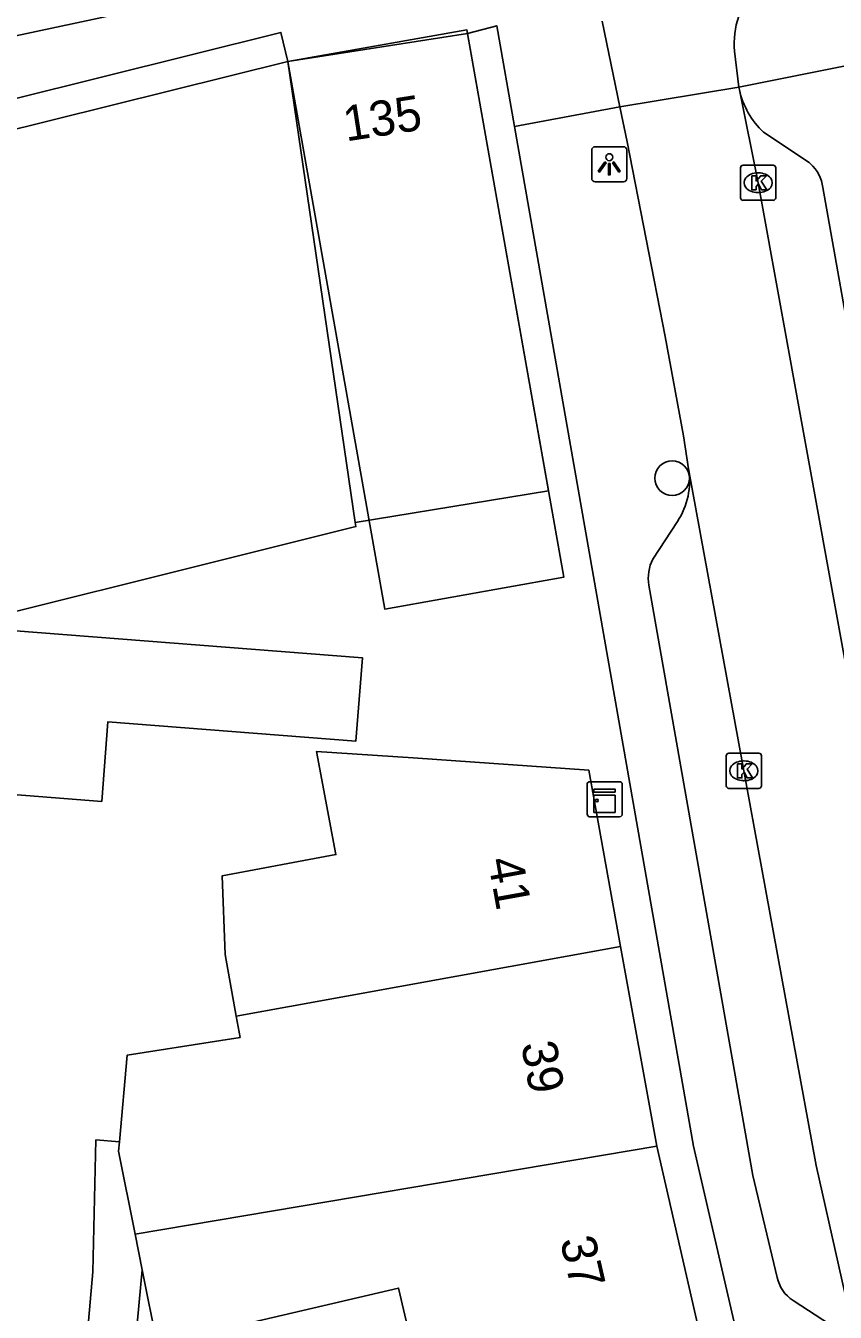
# Model space of a CAD drawing. Extents: x 160861 to 161308, y 384024 to 384878.
# Drawn here: x 160956.66 to 160979.67, y 384818.67 to 384855.22 of the extents above; entities that cross this region are included whole.
import ezdxf

# ---------------------------------------------------------------- set-up
doc = ezdxf.new("R2010")
doc.units = 0
for name, color, linetype in [('IMGEO_Boom', 7, 'Continuous'), ('IMGEO_Erf', 7, 'Continuous'), ('IMGEO_Kast', 7, 'Continuous'), ('IMGEO_Kolk', 7, 'Continuous'), ('IMGEO_Lichtpunt', 7, 'Continuous'), ('IMGEO_Pand', 7, 'Continuous'), ('IMGEO_Pand_nummerreeks', 7, 'Continuous'), ('IMGEO_Pand_vergunning_verleend', 7, 'Continuous'), ('IMGEO_Rijbaan_lokaal_open', 7, 'Continuous'), ('IMGEO_Voetpad_open', 7, 'Continuous')]:
    doc.layers.add(name, color=color, linetype=linetype)

msp = doc.modelspace()

# ---------------------------------------------------------------- linework, layer by layer
at = {"layer": 'IMGEO_Boom'}
msp.add_circle((160975.037, 384842.367), 0.489, dxfattribs=at)
at = {"layer": 'IMGEO_Erf'}
msp.add_lwpolyline([(160958.824, 384833.185), (160959.001, 384835.447), (160966.05, 384834.898), (160966.234, 384837.263), (160956.254, 384838.041), (160956.072, 384835.701), (160954.55, 384835.82), (160954.371, 384833.532), (160958.824, 384833.185)], dxfattribs=at)
at = {"layer": 'IMGEO_Kast'}
for p, q in [((160972.694, 384833.744), (160973.535, 384833.744)), ((160973.535, 384833.744), (160972.694, 384833.744)), ((160972.619, 384832.819), (160972.619, 384833.66)), ((160972.619, 384833.66), (160972.619, 384832.819)), ((160973.619, 384833.669), (160973.619, 384832.828)), ((160973.619, 384832.828), (160973.619, 384833.669)), ((160973.544, 384832.744), (160972.703, 384832.744)), ((160972.703, 384832.744), (160973.544, 384832.744))]:
    msp.add_line(p, q, dxfattribs=at)
for points in [[(160972.814, 384833.534), (160973.414, 384833.534), (160973.414, 384833.449), (160972.814, 384833.449), (160972.814, 384833.534)], [(160972.814, 384833.359), (160973.414, 384833.359), (160973.414, 384832.87), (160972.814, 384832.87), (160972.814, 384833.359)]]:
    msp.add_lwpolyline(points, dxfattribs=at)
msp.add_circle((160972.898, 384833.208), 0.0377, dxfattribs=at)
for centre, start, end in [((160972.697, 384833.666), 92.4484, 184.2845), ((160972.697, 384833.666), 92.4484, 184.2845), ((160973.541, 384833.666), 2.4484, 94.2845), ((160973.541, 384833.666), 2.4484, 94.2845), ((160972.697, 384832.822), 182.4484, 274.2845), ((160972.697, 384832.822), 182.4484, 274.2845), ((160973.541, 384832.822), 272.4484, 4.2845), ((160973.541, 384832.822), 272.4484, 4.2845)]:
    msp.add_arc(centre, 0.0779, start, end, dxfattribs=at)
at = {"layer": 'IMGEO_Kolk'}
for p, q in [((160977.054, 384851.26), (160977.906, 384851.26)), ((160976.979, 384850.334), (160976.979, 384851.186)), ((160977.467, 384851.04), (160977.492, 384851.04)), ((160977.98, 384851.186), (160977.98, 384850.334)), ((160977.906, 384850.26), (160977.054, 384850.26)), ((160977.49, 384850.48), (160977.465, 384850.48)), ((160976.574, 384833.627), (160976.574, 384834.479)), ((160976.649, 384834.553), (160977.501, 384834.553)), ((160977.575, 384834.479), (160977.575, 384833.627)), ((160977.062, 384834.333), (160977.087, 384834.333)), ((160977.085, 384833.773), (160977.06, 384833.773)), ((160977.501, 384833.553), (160976.649, 384833.553))]:
    msp.add_line(p, q, dxfattribs=at)
for points in [[(160977.054, 384851.26), (160977.906, 384851.26)], [(160976.979, 384850.334), (160976.979, 384851.186)], [(160977.3, 384850.96), (160977.423, 384850.96), (160977.423, 384850.809), (160977.553, 384850.96), (160977.717, 384850.96), (160977.571, 384850.809), (160977.724, 384850.56), (160977.572, 384850.56), (160977.487, 384850.724), (160977.423, 384850.657), (160977.423, 384850.56), (160977.3, 384850.56), (160977.3, 384850.96)], [(160977.98, 384851.186), (160977.98, 384850.334)], [(160977.906, 384850.26), (160977.054, 384850.26)], [(160976.574, 384833.627), (160976.574, 384834.479)], [(160976.649, 384834.553), (160977.501, 384834.553)], [(160977.575, 384834.479), (160977.575, 384833.627)], [(160976.895, 384834.253), (160977.018, 384834.253), (160977.018, 384834.102), (160977.148, 384834.253), (160977.312, 384834.253), (160977.166, 384834.102), (160977.319, 384833.853), (160977.167, 384833.853), (160977.082, 384834.017), (160977.018, 384833.95), (160977.018, 384833.853), (160976.895, 384833.853), (160976.895, 384834.253)], [(160977.501, 384833.553), (160976.649, 384833.553)]]:
    msp.add_lwpolyline(points, dxfattribs=at)
for centre, start, end in [((160977.056, 384851.184), 91.552, 178.448), ((160977.056, 384851.184), 91.552, 178.448), ((160977.904, 384851.184), 1.552, 88.448), ((160977.904, 384851.184), 1.552, 88.448), ((160977.056, 384850.336), 181.552, 268.448), ((160977.056, 384850.336), 181.552, 268.448), ((160977.904, 384850.336), 271.552, 358.448), ((160977.904, 384850.336), 271.552, 358.448), ((160976.651, 384834.477), 91.552, 178.448), ((160976.651, 384834.477), 91.552, 178.448), ((160977.499, 384834.477), 1.552, 88.448), ((160977.499, 384834.477), 1.552, 88.448), ((160976.651, 384833.629), 181.552, 268.448), ((160976.651, 384833.629), 181.552, 268.448), ((160977.499, 384833.629), 271.552, 358.448), ((160977.499, 384833.629), 271.552, 358.448)]:
    msp.add_arc(centre, 0.0765, start, end, dxfattribs=at)
for centre, major_axis, ratio, start_param, end_param in [((160977.466, 384850.76), (-0.387, 0.002), 0.722429, 4.712389, 7.853982), ((160977.491, 384850.76), (-0.39, 0.002), 0.717154, 1.570796, 4.712389), ((160977.061, 384834.053), (-0.387, 0.002), 0.722429, 4.712389, 7.853982), ((160977.086, 384834.053), (-0.39, 0.002), 0.717154, 1.570796, 4.712389)]:
    msp.add_ellipse(centre, major_axis=major_axis, ratio=ratio, start_param=start_param, end_param=end_param, dxfattribs=at)
at = {"layer": 'IMGEO_Lichtpunt'}
for p, q in [((160972.751, 384851.688), (160972.751, 384850.881)), ((160972.751, 384851.688), (160972.751, 384850.881)), ((160973.653, 384851.783), (160972.845, 384851.783)), ((160973.653, 384851.783), (160972.845, 384851.783)), ((160973.747, 384850.881), (160973.747, 384851.688)), ((160973.747, 384850.881), (160973.747, 384851.688)), ((160972.845, 384850.787), (160973.653, 384850.787)), ((160972.845, 384850.787), (160973.653, 384850.787))]:
    msp.add_line(p, q, dxfattribs=at)
for points in [[(160973.125, 384851.352), (160973.164, 384851.324), (160972.976, 384851.062), (160972.938, 384851.089), (160973.125, 384851.352)], [(160973.227, 384851.304), (160973.274, 384851.304), (160973.274, 384850.982), (160973.227, 384850.982), (160973.227, 384851.304)], [(160973.337, 384851.324), (160973.375, 384851.351), (160973.562, 384851.089), (160973.523, 384851.061), (160973.337, 384851.324)]]:
    msp.add_lwpolyline(points, dxfattribs=at)
msp.add_circle((160973.25, 384851.486), 0.0994, dxfattribs=at)
for centre, start, end in [((160972.845, 384851.688), 90, 180), ((160972.845, 384851.688), 90, 180), ((160973.653, 384851.688), 0, 90), ((160973.653, 384851.688), 0, 90), ((160972.845, 384850.881), 180, 270), ((160972.845, 384850.881), 180, 270), ((160973.653, 384850.881), 270, 0), ((160973.653, 384850.881), 270, 360)]:
    msp.add_arc(centre, 0.0946, start, end, dxfattribs=at)
at = {"layer": 'IMGEO_Pand'}
for points in [[(160969.221, 384855), (160964.114, 384854.203)], [(160966.03, 384841.11), (160971.52, 384842.007), (160969.221, 384855)], [(160964.114, 384854.203), (160940.701, 384848.385)], [(160964.114, 384854.203), (160966.03, 384841.11)], [(160936.502, 384833.624), (160961.197, 384839.783), (160966.048, 384840.993), (160966.03, 384841.11)], [(160973.571, 384829.064), (160972.664, 384834.076), (160967.676, 384834.418), (160964.93, 384834.605), (160965.479, 384831.671), (160962.245, 384831.065), (160962.335, 384828.832), (160962.647, 384827.086)], [(160962.647, 384827.086), (160973.571, 384829.064)], [(160973.571, 384829.064), (160974.598, 384823.39)], [(160959.326, 384823.509), (160959.546, 384825.972), (160962.205, 384826.393), (160962.755, 384826.48), (160962.647, 384827.086)], [(160959.773, 384820.887), (160959.303, 384823.247), (160959.326, 384823.509)], [(160974.598, 384823.39), (160959.773, 384820.887)], [(160974.598, 384823.39), (160975.854, 384817.922)], [(160959.974, 384819.878), (160959.773, 384820.887)], [(160968.016, 384816.123), (160967.262, 384819.358), (160960.397, 384817.757), (160959.974, 384819.878)]]:
    msp.add_lwpolyline(points, dxfattribs=at)
at = {"layer": 'IMGEO_Pand_vergunning_verleend'}
msp.add_lwpolyline([(160964.114, 384854.203), (160969.203, 384855.103), (160971.955, 384839.55), (160966.866, 384838.65), (160964.114, 384854.203)], dxfattribs=at)
at = {"layer": 'IMGEO_Rijbaan_lokaal_open'}
for points in [[(160973.048, 384855.354), (160973.549, 384852.917)], [(160976.934, 384853.479), (160976.811, 384854.494)], [(160973.549, 384852.917), (160976.934, 384853.479)], [(160976.934, 384853.479), (160976.949, 384853.403)], [(160983.723, 384817.77), (160982.15, 384825.052), (160978.754, 384843.764), (160977.479, 384850.76), (160976.949, 384853.403)], [(160975.504, 384842.631), (160975.364, 384843.569), (160974.84, 384846.396), (160973.754, 384851.919), (160973.549, 384852.917)], [(160980.396, 384817.197), (160979.13, 384822.843), (160975.504, 384842.631)]]:
    msp.add_lwpolyline(points, dxfattribs=at)
msp.add_arc((160979.147, 384854.725), 2.347, 87.207, 185.6429, dxfattribs=at)
at = {"layer": 'IMGEO_Voetpad_open'}
for points in [[(160964.035, 384856.587), (160963.14, 384856.385), (160937.579, 384850.927)], [(160889.382, 384835.598), (160889.152, 384835.522), (160888.676, 384836.263), (160928.998, 384846.338), (160933.394, 384847.435), (160963.917, 384855.031), (160964.114, 384854.203)], [(160969.221, 384855), (160970.051, 384855.218), (160970.553, 384852.358)], [(160980.11, 384854.108), (160976.934, 384853.479)], [(160973.549, 384852.917), (160970.553, 384852.358)], [(160970.553, 384852.358), (160975.639, 384823.391), (160980.654, 384801.69)], [(160977.635, 384852.197), (160978.934, 384851.332), (160978.97, 384851.301), (160979.039, 384851.233), (160979.101, 384851.159), (160979.157, 384851.08), (160979.206, 384850.996), (160979.247, 384850.908), (160979.279, 384850.817), (160979.304, 384850.723), (160979.32, 384850.627), (160980.401, 384844.553)], [(160974.485, 384840.067), (160975.188, 384841.137)], [(160978.026, 384819.662), (160977.327, 384822.558), (160974.375, 384839.328)], [(160959.326, 384823.509), (160958.656, 384823.569), (160958.566, 384819.819), (160956.275, 384793.744)], [(160959.974, 384819.878), (160959.274, 384812.307)], [(160979.533, 384818.317), (160978.474, 384819.007)]]:
    msp.add_lwpolyline(points, dxfattribs=at)
for centre, radius, start, end in [((160979.225, 384853.9), 2.33, 192.3092, 226.9552), ((160973.452, 384842.285), 2.081, 326.532, 9.5825), ((160975.578, 384839.527), 1.22, 153.6978, 189.3695), ((160979.005, 384819.851), 0.997, 190.9128, 237.8291)]:
    msp.add_arc(centre, radius, start, end, dxfattribs=at)

# ---------------------------------------------------------------- texts
at = {"layer": 'IMGEO_Pand_nummerreeks'}
for s, rotation, p in [('135', 8.8694, (160965.769, 384851.931)), ('41', 280.2615, (160969.793, 384831.522)), ('41', 280.2586, (160969.793, 384831.522)), ('39', 280.2615, (160970.74, 384826.291)), ('37', 282.9372, (160971.845, 384820.719))]:
    msp.add_text(s, height=1, rotation=rotation, dxfattribs=at).set_placement(p)

doc.saveas('drawing.dxf')
